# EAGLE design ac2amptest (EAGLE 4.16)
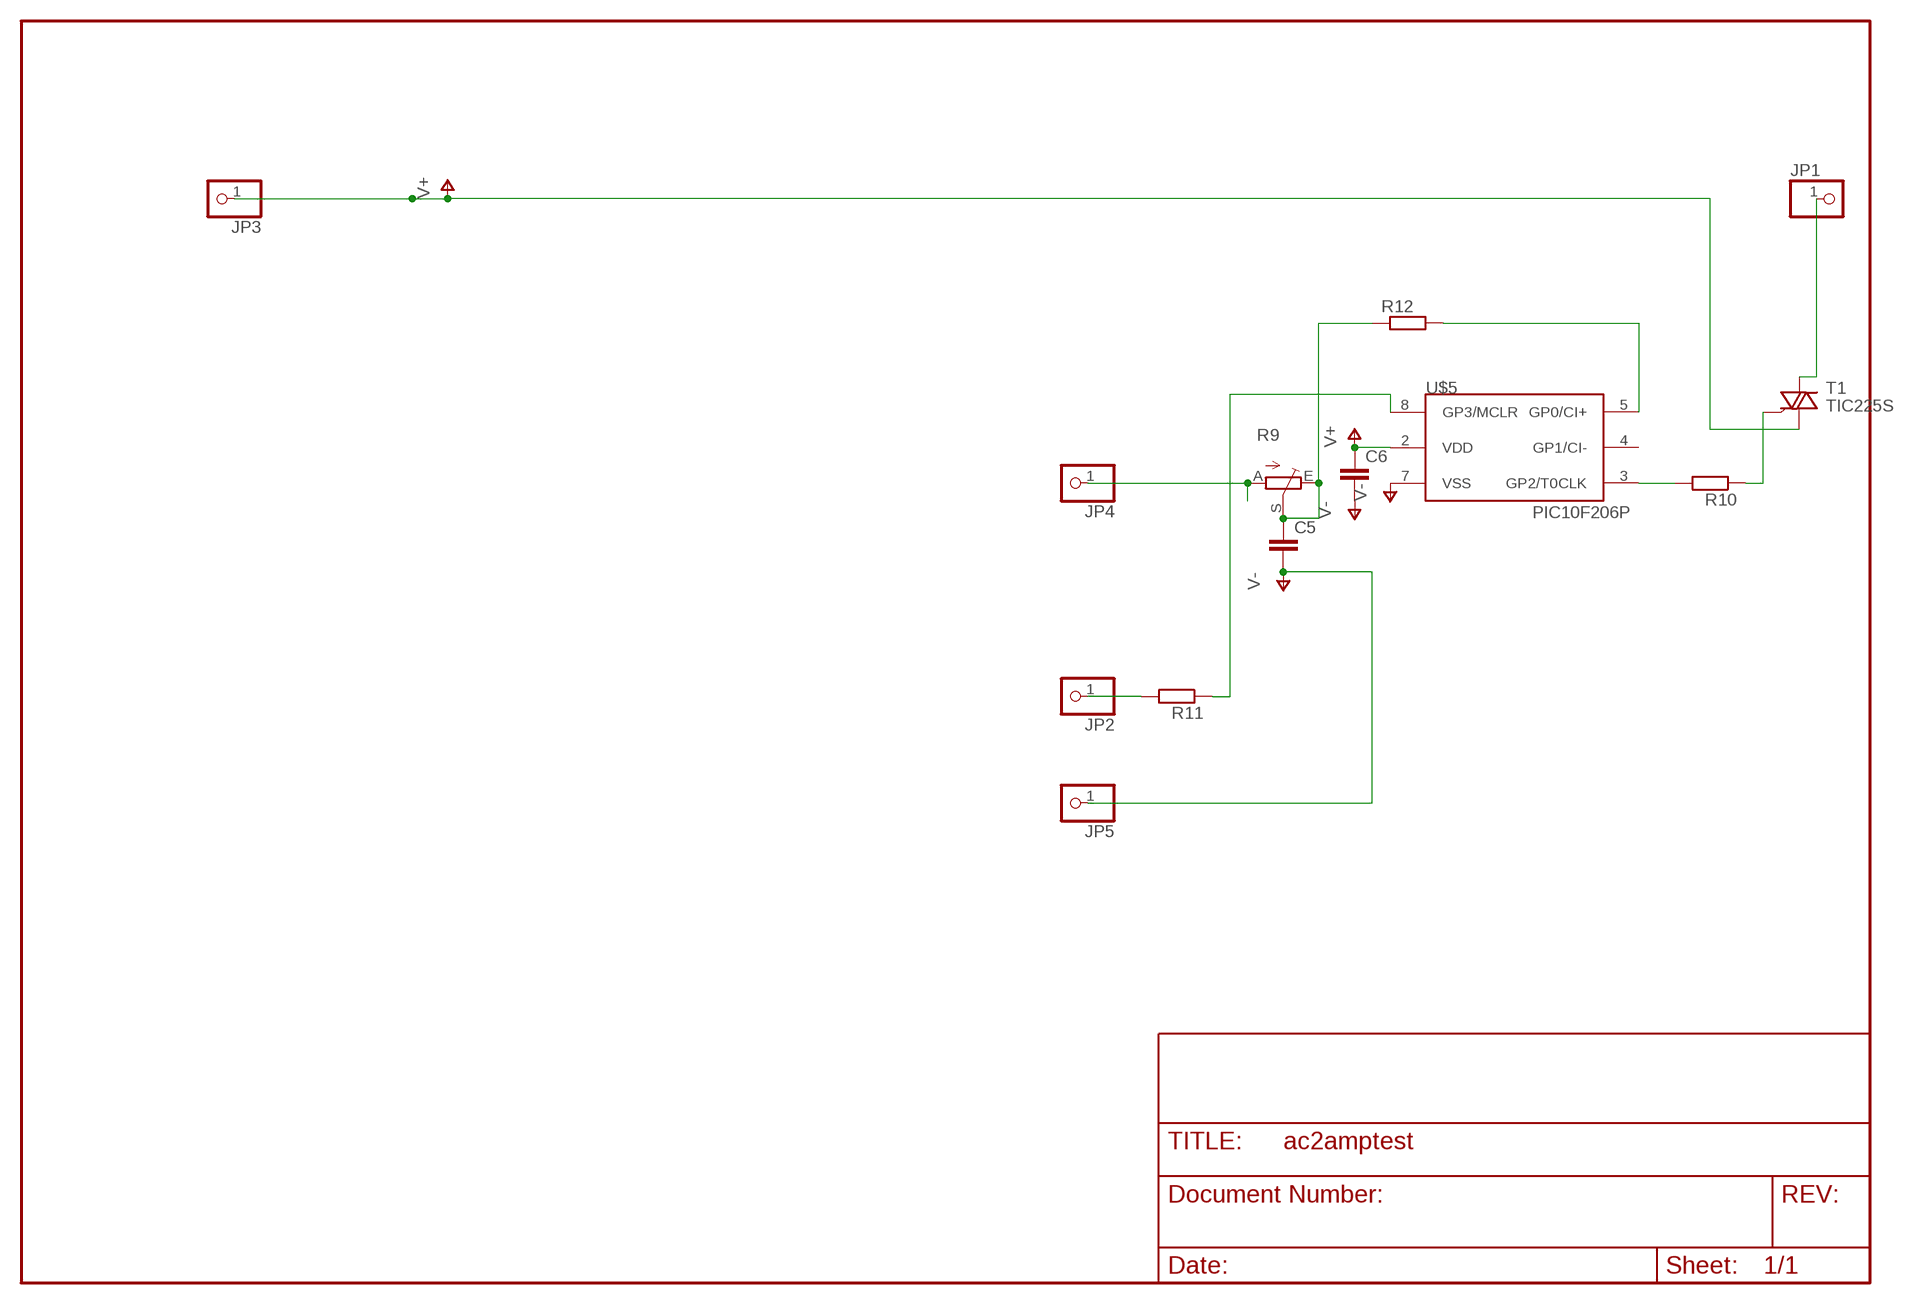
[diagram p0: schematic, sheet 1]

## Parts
C5  C-EU050-024X044  [C050-024X044]
C6  C-EU050-024X044  [C050-024X044]
JP1  PINHD-1X1  [1X01]
JP2  PINHD-1X1  [1X01]
JP3  PINHD-1X1  [1X01]
JP4  PINHD-1X1  [1X01]
JP5  PINHD-1X1  [1X01]
R9  TRIM_EU-LI15  [LI15]
R10  R-EU_0207/15  [0207/15]
R11  R-EU_0207/15  [0207/15]
R12  R-EU_0207/15  [0207/15]
T1  TIC225S  [TO220DS]
U$5  PIC10F206P  [DIL8]

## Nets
N$1: JP4.1 R9.A
N$3: JP2.1 R11.2
N$9: C5.1 R9.E R9.S R12.1
N$11: JP1.1 T1.A2
N$17: R11.1 U$5.8(GP3/MCLR)
N$19: R12.2 U$5.5(GP0/CI+)
N$20: R10.2 U$5.3(GP2/T0CLK)
N$21: R10.1 T1.G
V+: C6.1 JP3.1 T1.A1 U$5.2(VDD)
V-: C5.2 C6.2 JP5.1 U$5.7(VSS)
Unconnected: U$5.4(GP1/CI-)

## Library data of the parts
C5 C6 = rcl:C-EU: CAPACITOR, European symbol
JP1-JP5 = pinhead(2):PINHD-1X1: PIN HEADER
R9 = pot:TRIM_EU-: POTENTIOMETER
R10-R12 = rcl:R-EU_: RESISTOR, European symbol
T1 = triac:TIC225S: TRIAC
U$5 = microchip-3:PIC10F2*: uPC nW 0,25/0,5k Program Flash memory Comparator

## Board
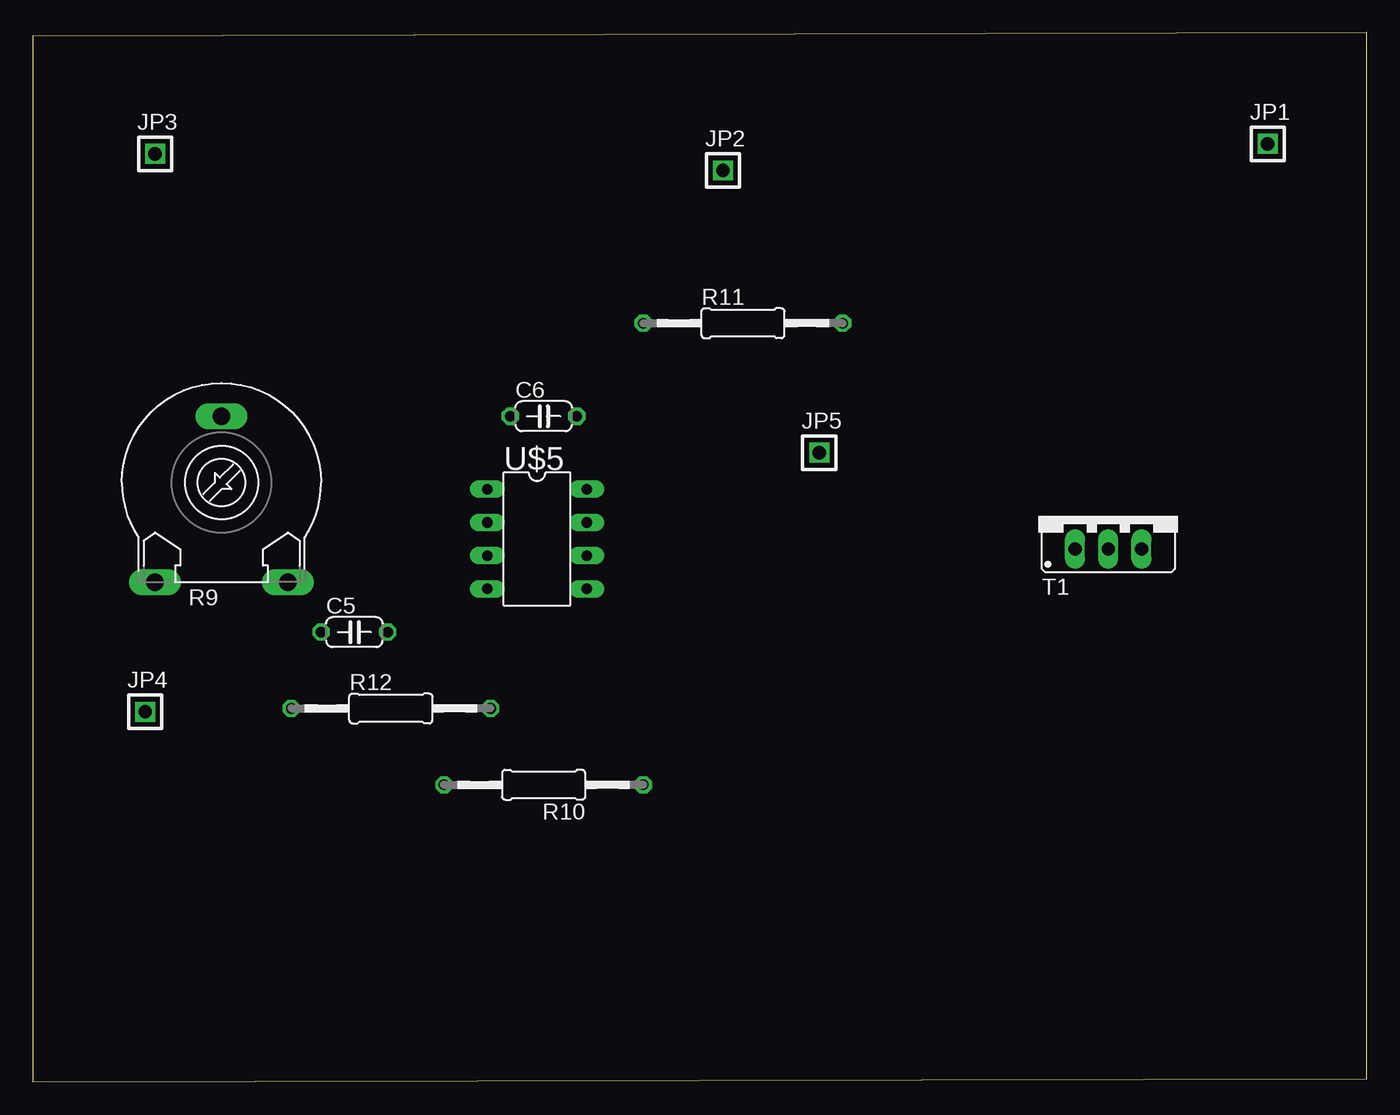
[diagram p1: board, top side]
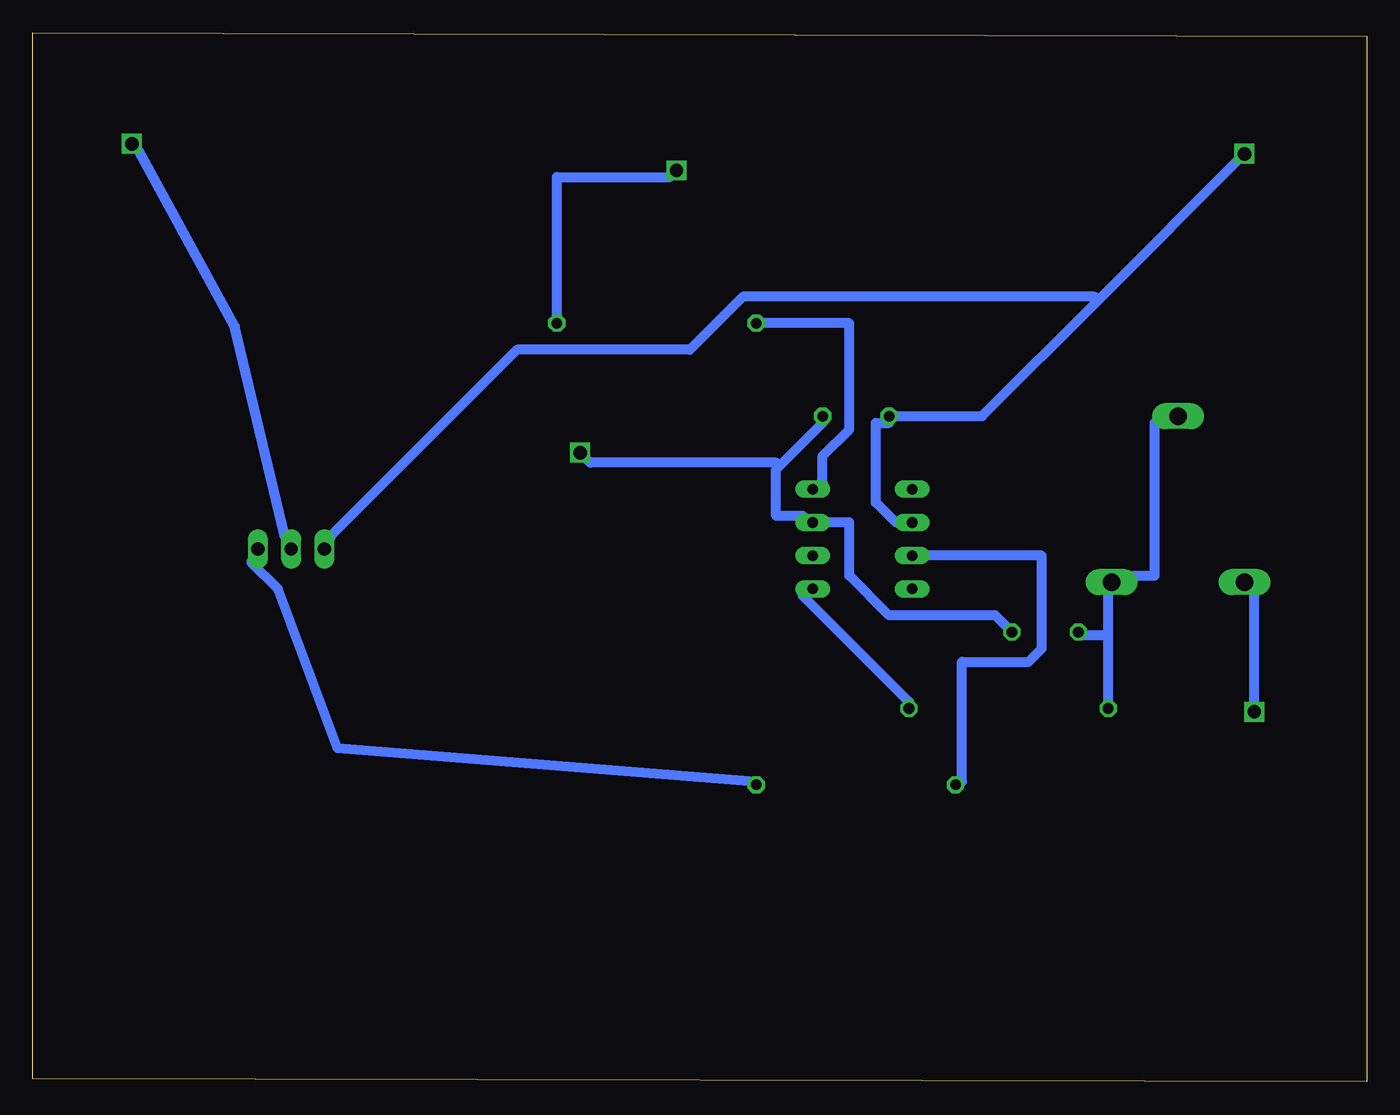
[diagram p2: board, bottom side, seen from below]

Size 102.03 x 80.25 mm. Coordinates in mm from the lower left corner, seen from the top.
Outline: 0,0 102.03,0.25 102.03,80.25 0,80 0,0
Copper layers (1*16): Top 0.035mm / dielectric 1.5mm / Bottom 0.035mm
Design rules "default": minimum track width 30mil, minimum drill 24mil, track to track 30mil, track to pad 30mil, pad to pad 8mil, via to via 8mil, smd to smd 8mil, copper to edge 40mil, drill to drill 20mil, minimum pad ring 10mil, minimum via ring 8mil, stop-mask expansion 4mil, vias tented up to drill 0mil, thermal gap 10mil

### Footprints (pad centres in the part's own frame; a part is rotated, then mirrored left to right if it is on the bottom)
C050-024X044 = drill 0.813 octagon: 1 -2.54,0; 2 2.54,0
1X01 = drill 1.016 square: 1 0,0
LI15 = drill 1.321 long: A -5.08,-7.62; E 5.08,-7.62; S 0,5.08
0207/15 = drill 0.813 octagon: 1 -7.62,0; 2 7.62,0
TO220DS = drill 1.016 long: A1 -2.54,-2.54; A2 0,-2.54; G 2.54,-2.54
DIL8 = drill 0.813 long: 1 -3.81,-3.81; 2 -1.27,-3.81; 3 1.27,-3.81; 4 3.81,-3.81; 5 3.81,3.81; 6 1.27,3.81; 7 -1.27,3.81; 8 -3.81,3.81

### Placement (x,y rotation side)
C5  24.6,34.41 0 top
C6  39.08,50.92 0 top
JP1  94.45,71.75 0 top
JP2  52.79,69.72 0 top
JP3  9.36,70.99 0 top
JP4  8.6,28.32 0 top
JP5  60.16,48.13 0 top
R9  14.44,45.84 0 top
R10  39.08,22.73 180 top
R11  54.32,58.03 0 top
R12  27.39,28.57 0 top
T1  82.26,43.3 0 top
U$5  38.57,41.52 270 top

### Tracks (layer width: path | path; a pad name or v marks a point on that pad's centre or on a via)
N$1
  Bottom 0.762: JP4.1 8.6,37.71 R9.A
N$3
  Bottom 0.762: R11.2 61.94,69.21 53.3,69.21 JP2.1
N$9
  Bottom 0.762: 19.77,34.16 21.81,34.16 C5.1 | R12.1 19.77,34.16 | 19.77,34.16 19.77,37.71 R9.E 17.74,38.73 16.22,38.73 16.22,50.41 R9.S
N$11
  Bottom 0.762: T1.A2 82.77,41.78 86.58,57.78 93.94,71.24 JP1.1
N$17
  Bottom 0.762: U$5.8 41.62,45.84 41.62,47.87 39.59,49.91 39.59,58.03 R11.1
N$19
  Bottom 0.762: R12.2 35.01,29.08 43.14,37.21 U$5.5
N$20
  Bottom 0.762: R10.2 30.95,22.98 30.95,32.13 25.87,32.13 24.85,33.14 24.85,40.25 U$5.3
N$21
  Bottom 0.762: R10.1 47.21,22.98 78.7,25.52 83.27,37.71 85.31,39.75 T1.G
V+
  Bottom 0.762: U$5.2 36.03,42.79 37.55,44.32 37.55,50.41 36.54,50.41 C6.1 29.43,50.92 20.54,59.81 | 20.54,59.81 JP3.1 | T1.A1 79.21,41.78 64.99,56 51.78,56 47.71,60.07 20.79,60.07 20.54,59.81
V-
  Bottom 0.762: C5.2 28.41,35.68 36.54,35.68 39.59,38.73 39.59,42.79 U$5.7 43.14,43.3 45.17,43.3 45.17,46.86 44.92,47.11 | 44.92,47.11 41.62,50.41 C6.2 | JP5.1 59.4,47.37 45.17,47.37 44.92,47.11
